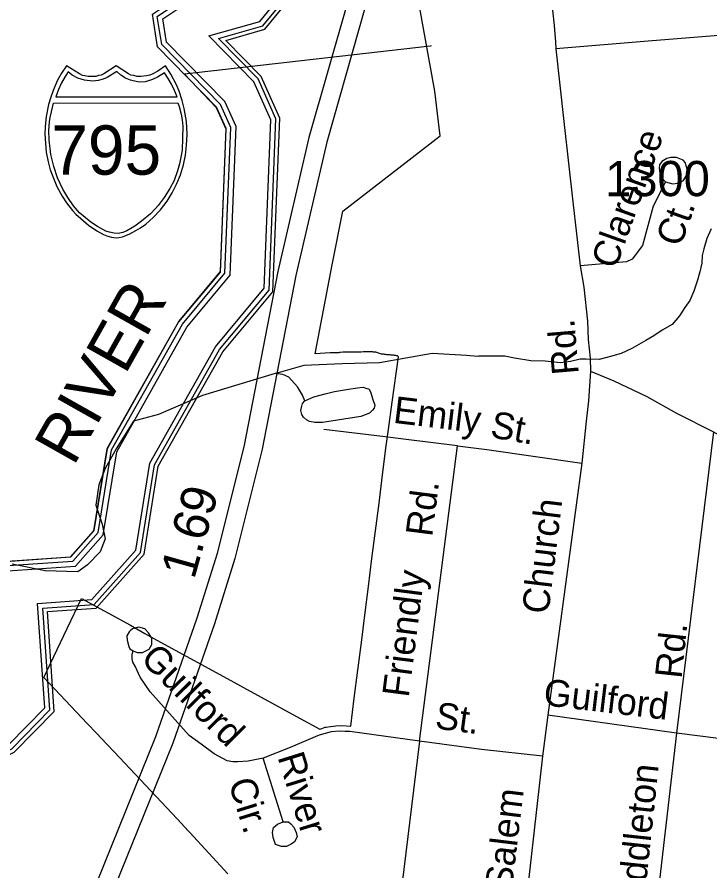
# Model space of a CAD drawing. Extents: x 2260773 to 2342389, y 552869 to 618546.
# Drawn here: x 2296402 to 2298862, y 604542 to 607573 of the extents above; entities that cross this region are included whole.
import ezdxf

# ---------------------------------------------------------------- set-up
doc = ezdxf.new("R2010")
doc.units = 0
for name, color, linetype in [('Exist Boundary Political City Limit New', 7, 'Continuous'), ('Exist Boundary Political Urban Extension UEB', 7, 'Continuous'), ('Exist Hydrographic Buffer Line', 7, 'Continuous'), ('Exist Hydrographic Misc Water Feature', 7, 'Continuous'), ('Exist Hydrographic River Shore', 7, 'Continuous'), ('Exist Hydrographic River Shore Label', 7, 'Continuous'), ('Exist Road Non-System Type 51', 7, 'Continuous'), ('Exist Road Non-System Type 51 Label', 7, 'Continuous'), ('Exist Road Primary Interstate Divided Center Attributed', 7, 'Continuous'), ('Exist Road Primary Interstate Service Mileage Tenths English Label', 7, 'Continuous'), ('Exist Road Primary Interstate Shield CELL', 7, 'Continuous'), ('Exist Road Primary Interstate Shield Number Label', 7, 'Continuous'), ('Exist Road Secondary Type 51 Attributed', 7, 'Continuous'), ('Exist Road Secondary Type 51 Label', 7, 'Continuous'), ('Exist Road Secondary Type 51 Number Label', 7, 'Continuous'), ('Map Preparation Boundary City Limit Buffer Line', 7, 'Continuous')]:
    doc.layers.add(name, color=color, linetype=linetype)

msp = doc.modelspace()

# ---------------------------------------------------------------- linework, layer by layer
at = {"layer": 'Exist Boundary Political City Limit New'}
for points in [[(2297696.2, 606376.5), (2297693.2, 606377.2), (2297689.5, 606378.7), (2297685.8, 606379.9), (2297683, 606380.9), (2297680, 606381.8), (2297676.2, 606382.8), (2297672.2, 606383.1), (2297668.2, 606383.4), (2297664.2, 606384.2), (2297660.5, 606384.6), (2297657.5, 606384.5), (2297654.5, 606384.4), (2297646.5, 606384.2), (2297642.5, 606384.3), (2297638.5, 606384.5), (2297635.5, 606384.4), (2297632.5, 606384.2), (2297624.5, 606383.8), (2297621.5, 606383.6), (2297618.5, 606383.5), (2297614.5, 606383.5), (2297610.5, 606383.6), (2297606.5, 606383.7), (2297602.5, 606383.8), (2297598.5, 606383.8), (2297595.5, 606383.8), (2297592.5, 606383.8), (2297588.5, 606383.6), (2297584.5, 606383.3), (2297580.5, 606383.1), (2297576.5, 606383.2), (2297572.5, 606383.5), (2297568.5, 606383.6), (2297564.5, 606383.7), (2297561.5, 606383.5), (2297558.5, 606383.2), (2297550.5, 606382.2), (2297547.5, 606381.8), (2297544.5, 606381.4), (2297540.5, 606381.2), (2297536.5, 606381.2), (2297532.5, 606381.3), (2297522.5, 606381.3), (2297514.5, 606381.1), (2297460.8, 606377.7), (2297521.5, 606693.6), (2297559.5, 606884.2), (2297904.8, 607151.4), (2297886.2, 607310.1), (2297774, 607926.1)], [(2297151, 604531.2), (2297015.2, 604677.7), (2297011, 604682.2), (2296970.5, 604725.9), (2296747.2, 604964.4), (2296719.8, 604993.1), (2296685.5, 605029.5), (2296651.5, 605065.4), (2296496.8, 605228.8), (2296580.2, 605402.7), (2296631.5, 605508.9), (2296805.2, 605413.8), (2296856.2, 605384.6), (2296899.2, 605360.9), (2297161.5, 605217.2), (2297206.2, 605192.8), (2297407.2, 605083.2), (2297477.2, 605044.9), (2297484.5, 605047.6), (2297496, 605051.9), (2297500, 605052.4), (2297515.2, 605054.7), (2297534, 605056.9), (2297555, 605057.8), (2297587.5, 605055.6), (2297599.8, 605154.9), (2297612.2, 605253.8), (2297624.8, 605352.5), (2297637.2, 605449.9), (2297650, 605550.9), (2297662.5, 605650.3), (2297675, 605749.3), (2297687.5, 605847.4), (2297700, 605948.2), (2297713, 606050.9), (2297721.5, 606109.2), (2297734.5, 606205.7), (2297756.2, 606366.8), (2297752.8, 606370.2), (2297750, 606370.9), (2297747, 606371.3), (2297743, 606371.9), (2297739, 606372.4), (2297735, 606372.8), (2297731, 606373.2), (2297727, 606373.4), (2297723, 606373.6), (2297719, 606373.8), (2297715, 606374.2), (2297711.2, 606374.8), (2297707.2, 606375.2), (2297703.2, 606375.8), (2297699.2, 606376.1), (2297696.2, 606376.5)]]:
    msp.add_lwpolyline(points, dxfattribs=at)
at = {"layer": 'Exist Boundary Political Urban Extension UEB'}
msp.add_line((2297872.5, 607470.4), (2297868.7, 607470), dxfattribs=at)
msp.add_lwpolyline([(2297868.7, 607470), (2296996.9, 607370.9), (2297109.4, 607251.9), (2297143.4, 607175.8), (2297123.3, 606667.8), (2296975.3, 606490.5), (2296721.4, 606039.8), (2296674.3, 605748.9), (2296591.4, 605655.4), (2296296, 605634.7)], dxfattribs=at)
at = {"layer": 'Exist Hydrographic Buffer Line'}
for points in [[(2296475, 605491.4), (2296668, 605505), (2296823.6, 605680.5), (2296873.6, 605988.8), (2297106.7, 606402.6), (2297279.8, 606610), (2297303.4, 607208.1), (2297242.9, 607343.6), (2297083.4, 607506.2), (2297264.1, 607557.4), (2297395.8, 607717.8), (2297494.3, 607907.7), (2297504.1, 608392.7)], [(2296494.4, 605474.7), (2296676.6, 605487.4), (2296840.6, 605672.5), (2296890.9, 605982.8), (2297121.6, 606392.3), (2297297.6, 606603.1), (2297321.7, 607211.6), (2297258, 607353.9), (2297117.7, 607497.1), (2297274.5, 607541.5), (2297411, 607707.8), (2297512.3, 607903.2), (2297522.4, 608402.3)], [(2296298.6, 605620.6), (2296600.6, 605641.8), (2296690.8, 605743.6), (2296738.2, 606036.2), (2296990, 606483.2), (2297140.5, 606663.6), (2297161, 607180.7), (2297124.3, 607262.8), (2296915.9, 607475.3), (2296900.2, 607575.4), (2296964.8, 607619.3), (2297183, 607681.2), (2297277.2, 607795.9), (2297353.7, 607943.5), (2297359.6, 608229.5)], [(2296299.9, 605601.9), (2296609.5, 605623.6), (2296708.4, 605735.2), (2296756.2, 606030), (2297005.5, 606472.5), (2297159, 606656.5), (2297179.9, 607184.3), (2297140, 607273.5), (2296933.5, 607484.2), (2296920.5, 607566.6), (2296972.8, 607602.1), (2297193.8, 607664.7), (2297293, 607785.5), (2297372.4, 607938.8), (2297378.3, 608229.1)], [(2294622.7, 604572.8), (2294697.8, 604716.4), (2294813.4, 604644.1), (2295136.8, 604692.7), (2295597, 604923.2), (2296195.9, 604904.5), (2296373.2, 604989.9), (2296500.5, 605120.2), (2296475, 605491.4)], [(2294638.6, 604563.9), (2294704.9, 604690.5), (2294809.4, 604625.1), (2295142.4, 604675.1), (2295601.1, 604904.8), (2296199.8, 604886.1), (2296384, 604974.9), (2296519.2, 605113.3), (2296494.4, 605474.7)]]:
    msp.add_lwpolyline(points, dxfattribs=at)
at = {"layer": 'Exist Hydrographic Misc Water Feature'}
for points in [[(2298866.4, 606821.2), (2298851, 606787), (2298841.2, 606750.8), (2298835.4, 606726.9), (2298833.8, 606698.8), (2298826.2, 606668.7), (2298818.6, 606638.6), (2298805.1, 606600.5), (2298791.3, 606566.5), (2298773.7, 606542.4), (2298754.2, 606512), (2298728.4, 606481.9), (2298692.7, 606461.3), (2298663, 606441), (2298634.7, 606425), (2298585.3, 606396.3), (2298547.5, 606378.1), (2298509.6, 606367.6), (2298469.6, 606357), (2298423.5, 606358.6), (2298401.7, 606358.3), (2298367.7, 606350), (2298332, 606345.7), (2298277.7, 606351), (2298226, 606352.3), (2298168.2, 606361.8), (2298133.7, 606369.5), (2298100.1, 606369.3), (2298074.1, 606368.7), (2298042.3, 606368.6), (2298038.4, 606368.4)], [(2298038.4, 606368.4), (2297998.2, 606372), (2297876, 606379), (2297689, 606345.2), (2297557.1, 606341.9), (2297421, 606336.4), (2297329.1, 606309.7), (2297319.3, 606307.6)], [(2297319.3, 606307.6), (2297189.5, 606268.3), (2297060.3, 606229.4), (2296904.9, 606161.9), (2296815.2, 606138.9)], [(2297424.3, 606210.6), (2297415.6, 606230.6), (2297397.8, 606260.5), (2297367.7, 606294.2), (2297345.5, 606304), (2297319.3, 606307.6)], [(2297424.3, 606210.6), (2297456, 606225), (2297496, 606235.6), (2297529.6, 606243.9), (2297579.5, 606252.2), (2297611.7, 606256.6), (2297631.6, 606258.5), (2297643.7, 606254.7), (2297651.4, 606252.7), (2297657.4, 606242.8), (2297666, 606215.2), (2297672.2, 606195.2), (2297669.9, 606185), (2297664.4, 606176.9), (2297654.3, 606167.1), (2297622.9, 606154.8), (2297540.7, 606142), (2297487.2, 606133.4), (2297459.1, 606133.2), (2297440.9, 606136.8), (2297430.4, 606142.8), (2297418.9, 606152.7), (2297413, 606162.5), (2297410.5, 606176.6), (2297412.2, 606186.5), (2297416.3, 606200.5), (2297424.3, 606210.6)], [(2296815.2, 606138.9), (2296754.3, 606040.7), (2296715, 605970.3), (2296693.2, 605911.9), (2296682.2, 605839.8), (2296704.9, 605772.3), (2296715.4, 605720.5), (2296698, 605674), (2296652.4, 605627.7), (2296618.6, 605603.6), (2296502.1, 605606.6), (2296384.4, 605631.2)]]:
    msp.add_lwpolyline(points, dxfattribs=at)
at = {"layer": 'Exist Hydrographic River Shore'}
for points in [[(2296509.9, 605462.2), (2296683.1, 605474.4), (2296853.3, 605666.4), (2296903.9, 605978.2), (2297132.8, 606384.6), (2297310.9, 606598), (2297335.3, 607214.3), (2297269.4, 607361.6), (2297143.2, 607490.3), (2297282.2, 607529.7), (2297422.3, 607700.3), (2297525.7, 607899.7), (2297536.1, 608412.7)], [(2296297.5, 605636.5), (2296593, 605657.2), (2296675.8, 605750.7), (2296723, 606041.6), (2296976.8, 606492.3), (2297124.9, 606669.6), (2297145, 607177.6), (2297110.9, 607253.7), (2296901, 607467.8), (2296882.9, 607582.9), (2296958, 607633.9), (2297173.9, 607695.1), (2297263.9, 607804.7), (2297337.9, 607947.5), (2297343.7, 608229.8)], [(2294651.5, 604557.2), (2294710.5, 604669.8), (2294806.3, 604609.9), (2295146.8, 604661.1), (2295604.3, 604890.1), (2296202.9, 604871.5), (2296392.6, 604962.9), (2296534.2, 605107.8), (2296509.9, 605462.2)]]:
    msp.add_lwpolyline(points, dxfattribs=at)
at = {"layer": 'Exist Road Non-System Type 51'}
for p, q in [((2297699.9, 606083.4), (2297491.4, 606108.8)), ((2298875.5, 606100.5), (2298744.2, 605031.1)), ((2297783.9, 606073.2), (2297699.9, 606083.4)), ((2297965.7, 606051.1), (2297783.9, 606073.2)), ((2297831.6, 605002.4), (2297965.7, 606051.1)), ((2298744.2, 605031.1), (2298286.5, 605094.4)), ((2297346.6, 604716), (2297276.6, 604941.3))]:
    msp.add_line(p, q, dxfattribs=at)
for points in [[(2298704.3, 606988.5), (2298730.4, 606980.8), (2298748.3, 606983.1), (2298768.3, 606993.3), (2298782, 607015.5), (2298781.7, 607033.5), (2298777.6, 607045.3), (2298775.6, 607055.2), (2298767.4, 607065.3), (2298743.4, 607074.9), (2298723.4, 607074.7), (2298709.4, 607070.6), (2298691.6, 607060.4), (2298683.7, 607048.3), (2298681.8, 607036.2), (2298684.1, 607018.3), (2298692.1, 607002.4), (2298704.3, 606988.5)], [(2298704.3, 606988.5), (2298661.2, 606902.2), (2298623.4, 606762), (2298586.4, 606714), (2298566.4, 606703.7), (2298402.1, 606689.7)], [(2297965.7, 606051.1), (2298070.3, 606037.9), (2298407.2, 605989.2)], [(2299263.3, 605872.5), (2299145.6, 604980.3), (2298744.2, 605031.1)], [(2296804, 605393.6), (2296800.5, 605390.6), (2296792.6, 605376.6), (2296792.9, 605360.6), (2296799.1, 605338.7), (2296803.1, 605330.6), (2296815.1, 605322.8)], [(2296881, 605348.3), (2296880.8, 605367.4), (2296868.6, 605387.3), (2296856.5, 605401.1), (2296834.4, 605406.9), (2296812.5, 605400.8), (2296804, 605393.6)], [(2296833.7, 605316.9), (2296847.2, 605317.1), (2296871, 605329.2), (2296881, 605345.4), (2296881, 605348.3)], [(2297276.6, 604941.3), (2297222.6, 604930.8), (2297186.8, 604928.6), (2297168.8, 604928.3), (2297148.7, 604932.1), (2297102.4, 604957.7), (2297056.1, 604991.2), (2297014, 605022.8), (2296874.5, 605177.4), (2296840, 605229.1), (2296821.6, 605268.9), (2296813.5, 605282.8), (2296811.6, 605294.7), (2296811.3, 605310.7), (2296815.1, 605322.8)], [(2296815.1, 605322.8), (2296829.2, 605316.9), (2296833.7, 605316.9)], [(2297566.3, 605036.9), (2297547.5, 605037.8), (2297517.4, 605035.6), (2297475.6, 605023.1), (2297469.6, 605020.6)], [(2297831.6, 605002.4), (2297583.4, 605036.1), (2297566.3, 605036.9)], [(2298744.2, 605031.1), (2298663.6, 604335), (2298650.9, 604270), (2298635.4, 604229), (2298595.8, 604175.3), (2298512.5, 604069.3), (2298433.4, 603983), (2298395.9, 603952.3), (2298343, 603932.1), (2298273.7, 603926.5), (2298150.1, 603935.3)], [(2297469.6, 605020.6), (2297372.2, 604980.2), (2297276.6, 604941.3)], [(2297831.6, 605002.4), (2297761.1, 604432.1), (2297763.3, 604412.2), (2297767.4, 604400.2), (2297777.5, 604384.4), (2297789.5, 604374.5), (2297823.7, 604366.8), (2298053.4, 604323.7), (2298196.1, 604308.1)], [(2298268.5, 604949), (2298051.7, 604972.6), (2297831.6, 605002.4)], [(2297346.6, 604716), (2297366.6, 604716.2), (2297374.6, 604708.4), (2297384.8, 604696.4), (2297393, 604678.5), (2297397.1, 604662.6), (2297387.3, 604644.6), (2297375.4, 604636.4), (2297359.4, 604628.2), (2297341.4, 604628.1), (2297319.4, 604635.8), (2297311.1, 604659.7), (2297309, 604677.8), (2297312.8, 604695.7), (2297326.6, 604707.8), (2297346.6, 604716)]]:
    msp.add_lwpolyline(points, dxfattribs=at)
at = {"layer": 'Exist Road Primary Interstate Divided Center Attributed'}
for points in [[(2298844.5, 609852.1), (2298779.6, 609757.5), (2298564.9, 609447.7), (2298280.6, 609029.8), (2298078.5, 608714.6), (2297910.7, 608420), (2297811.4, 608214.4), (2297736.1, 608043.2), (2297575.1, 607625.2), (2297438.1, 607145.6), (2297328.5, 606669.4), (2297208.7, 606052.8), (2297112.8, 605669.1), (2297040.9, 605439.5), (2296893.6, 605018.2), (2296605.9, 604305.6), (2296386.7, 603730), (2296248.2, 603378.4), (2296202.7, 603264.5), (2296044.3, 602853), (2295787.4, 602202.1), (2295553.8, 601595.1)], [(2298862.1, 609753.4), (2298618.9, 609410.6), (2298335.4, 608993.6), (2298134.7, 608680.6), (2297968.8, 608389.4), (2297871, 608186.9), (2297796.7, 608018.1), (2297637.4, 607604.4), (2297501.7, 607129.2), (2297392.7, 606655.8), (2297272.7, 606038.5), (2297176, 605651.3), (2297103.1, 605418.9), (2296955, 604995), (2296667, 604281.6), (2296448.1, 603706.8), (2296328.1, 603387.7), (2296105.3, 602828.8), (2295848.5, 602178.3), (2295615.8, 601573.6)]]:
    msp.add_lwpolyline(points, dxfattribs=at)
at = {"layer": 'Exist Road Primary Interstate Shield CELL'}
for points in [[(2296754.2, 606789.7), (2296763.7, 606790.6), (2296776.5, 606793.1), (2296788.8, 606797.1), (2296802.9, 606803.4), (2296823.8, 606814.9), (2296840.5, 606824.7), (2296859.9, 606837.7), (2296886, 606861.4), (2296912, 606888.9), (2296935, 606919.9), (2296953.3, 606948.9), (2296969.4, 606982.1), (2296982.8, 607013), (2296993.5, 607048.3), (2297000.5, 607082.5), (2297004.1, 607118.2), (2297006.5, 607157.8), (2297003.8, 607202.4), (2296996, 607247.9), (2296988.8, 607276.3), (2296977.7, 607310.2), (2296968.7, 607331.9), (2296947.9, 607370.3), (2296929.2, 607399.9), (2296901.9, 607380.7), (2296884.2, 607371.3), (2296873.3, 607366.4), (2296862.2, 607364.3), (2296841.7, 607361.8), (2296828.8, 607362.3), (2296816.8, 607365.1), (2296806.7, 607367.3), (2296798.5, 607371.3), (2296754.2, 607399.9), (2296710, 607371.3), (2296700.7, 607367), (2296691.2, 607365.1), (2296682, 607362.5), (2296666.9, 607361.8), (2296655.3, 607362.1), (2296643.5, 607364.3), (2296634.1, 607366.2), (2296623.6, 607371.3), (2296578.4, 607399.9), (2296560.7, 607374.2), (2296546.2, 607348.8), (2296530.9, 607312.9), (2296521.3, 607285), (2296514.5, 607262.2), (2296506.2, 607220.2), (2296501.9, 607183.7), (2296501.1, 607157.8), (2296505.9, 607093.3), (2296512.9, 607058.9), (2296520.1, 607031.2), (2296544, 606971.1), (2296561.9, 606937.5), (2296577.3, 606913.3), (2296598.9, 606886.2), (2296610.6, 606873.2), (2296655.4, 606834), (2296685.4, 606813.6), (2296709.3, 606800.7), (2296720.5, 606796.4), (2296738.1, 606791.5)], [(2296583.8, 607379.2), (2296572.8, 607362.3), (2296560.1, 607339.4), (2296550, 607315.7), (2296539.6, 607289.6), (2296971.2, 607289.4), (2296961.2, 607311.9), (2296950.4, 607334.4), (2296939.1, 607354.9), (2296925.4, 607374.8), (2296901.2, 607359.6), (2296883.6, 607351.3), (2296869.4, 607346.4), (2296857.4, 607343.7), (2296838.8, 607342.2), (2296830.5, 607342.7), (2296804.6, 607348.6), (2296787, 607355.7), (2296770.3, 607366.9), (2296756.8, 607379.6), (2296722.6, 607358.9), (2296707.5, 607352.2), (2296690, 607347.8), (2296670.9, 607345.4), (2296641.5, 607348.6), (2296618.4, 607356.5), (2296598.5, 607366.9)], [(2296973.7, 607268.1), (2296978.4, 607255.9), (2296984.7, 607228.9), (2296988.1, 607208.1), (2296991.5, 607184.1), (2296990.3, 607142.9), (2296988.3, 607100.4), (2296984.4, 607075.1), (2296979.2, 607052.2), (2296972, 607026.7), (2296960.5, 606992.9), (2296944.6, 606964.3), (2296924.7, 606932.4), (2296903.2, 606904.6), (2296893.9, 606893), (2296876.2, 606874.3), (2296844, 606848.5), (2296820.4, 606830.9), (2296792.3, 606814.2), (2296777.9, 606807.9), (2296761.3, 606804.4), (2296747.6, 606805.4), (2296731, 606809.8), (2296717.5, 606813.4), (2296688.1, 606829.4), (2296664.2, 606845.3), (2296624.4, 606877.9), (2296603, 606903), (2296582.9, 606932.4), (2296565.1, 606962.5), (2296546, 607002.2), (2296532.5, 607042.1), (2296522.8, 607085.2), (2296516.2, 607137.8), (2296515.4, 607169.9), (2296517.4, 607200.7), (2296520.3, 607216.9), (2296524.2, 607236.9), (2296532.1, 607267.9)]]:
    msp.add_lwpolyline(points, close=True, dxfattribs=at)
at = {"layer": 'Exist Road Secondary Type 51 Attributed'}
for points in [[(2298326.3, 607902.4), (2298320.6, 607880.8), (2298315.2, 607857.3), (2298309.1, 607821.1), (2298305.7, 607792.5), (2298302.5, 607756.6), (2298300.3, 607714.1), (2298299.3, 607663.6), (2298304.1, 607597.5), (2298309.5, 607543.5), (2298314.2, 607485.4), (2298315.5, 607460.1)], [(2302573.1, 607056.5), (2302555.7, 607059.5), (2302514.8, 607063.8), (2302204.4, 607120.2), (2301760.8, 607205.2), (2301372.1, 607283.2), (2300991.4, 607343.2), (2300723.5, 607379.8), (2300350.2, 607435.5), (2300073.5, 607473.6), (2299877.3, 607500), (2299662.1, 607516.6), (2299504.7, 607526.3), (2299403.7, 607530.7), (2299340.7, 607530.7), (2299273.4, 607532.2), (2299137.4, 607527.2), (2299130.2, 607526.9), (2298642.9, 607487.6), (2298315.5, 607460.1)], [(2298315.5, 607460.1), (2298344.1, 607202.6), (2298375.3, 606917), (2298402.1, 606689.7), (2298414.6, 606613.7), (2298427.8, 606493.8), (2298430.5, 606427.9), (2298436.9, 606362.3), (2298439, 606315.7)], [(2298439, 606315.7), (2298430.9, 606210.1), (2298423.6, 606138), (2298407.2, 605989.2), (2298286.5, 605094.4), (2298268.5, 604949), (2298196.1, 604308.1), (2298150.1, 603935.3), (2298124.7, 603738.1), (2298109.9, 603570.6), (2298110.1, 603317.9), (2298127.6, 603170.2), (2298167.9, 602956.8), (2298250.4, 602544), (2298308.7, 602254.2), (2298357.8, 602203.1), (2298421.4, 602171.3), (2298523.1, 602133.1)], [(2298439, 606315.7), (2298521.7, 606281.8), (2298638.2, 606225.6), (2298744.2, 606166.2), (2298875.5, 606100.5), (2299197.6, 605916), (2299263.3, 605872.5), (2299460.4, 605743.2), (2299617.2, 605643.6), (2299786.7, 605531.2), (2299909.6, 605444.2)]]:
    msp.add_lwpolyline(points, dxfattribs=at)
at = {"layer": 'Map Preparation Boundary City Limit Buffer Line'}
for points in [[(2297696.2, 606376.5), (2297693.2, 606377.2), (2297689.5, 606378.7), (2297685.8, 606379.9), (2297683, 606380.9), (2297680, 606381.8), (2297676.2, 606382.8), (2297672.2, 606383.1), (2297668.2, 606383.4), (2297664.2, 606384.2), (2297660.5, 606384.6), (2297657.5, 606384.5), (2297654.5, 606384.4), (2297646.5, 606384.2), (2297642.5, 606384.3), (2297638.5, 606384.5), (2297635.5, 606384.4), (2297632.5, 606384.2), (2297624.5, 606383.8), (2297621.5, 606383.6), (2297618.5, 606383.5), (2297614.5, 606383.5), (2297610.5, 606383.6), (2297606.5, 606383.7), (2297602.5, 606383.8), (2297598.5, 606383.8), (2297595.5, 606383.8), (2297592.5, 606383.8), (2297588.5, 606383.6), (2297584.5, 606383.3), (2297580.5, 606383.1), (2297576.5, 606383.2), (2297572.5, 606383.5), (2297568.5, 606383.6), (2297564.5, 606383.7), (2297561.5, 606383.5), (2297558.5, 606383.2), (2297550.5, 606382.2), (2297547.5, 606381.8), (2297544.5, 606381.4), (2297540.5, 606381.2), (2297536.5, 606381.2), (2297532.5, 606381.3), (2297522.5, 606381.3), (2297514.5, 606381.1), (2297460.8, 606377.7), (2297521.5, 606693.6), (2297559.5, 606884.2), (2297904.8, 607151.4), (2297886.2, 607310.1), (2297774, 607926.1)], [(2297151, 604531.2), (2297015.2, 604677.7), (2297011, 604682.2), (2296970.5, 604725.9), (2296747.2, 604964.4), (2296719.8, 604993.1), (2296685.5, 605029.5), (2296651.5, 605065.4), (2296496.8, 605228.8), (2296580.2, 605402.7), (2296631.5, 605508.9), (2296805.2, 605413.8), (2296856.2, 605384.6), (2296899.2, 605360.9), (2297161.5, 605217.2), (2297206.2, 605192.8), (2297407.2, 605083.2), (2297477.2, 605044.9), (2297484.5, 605047.6), (2297496, 605051.9), (2297500, 605052.4), (2297515.2, 605054.7), (2297534, 605056.9), (2297555, 605057.8), (2297587.5, 605055.6), (2297599.8, 605154.9), (2297612.2, 605253.8), (2297624.8, 605352.5), (2297637.2, 605449.9), (2297650, 605550.9), (2297662.5, 605650.3), (2297675, 605749.3), (2297687.5, 605847.4), (2297700, 605948.2), (2297713, 606050.9), (2297721.5, 606109.2), (2297734.5, 606205.7), (2297756.2, 606366.8), (2297752.8, 606370.2), (2297750, 606370.9), (2297747, 606371.3), (2297743, 606371.9), (2297739, 606372.4), (2297735, 606372.8), (2297731, 606373.2), (2297727, 606373.4), (2297723, 606373.6), (2297719, 606373.8), (2297715, 606374.2), (2297711.2, 606374.8), (2297707.2, 606375.2), (2297703.2, 606375.8), (2297699.2, 606376.1), (2297696.2, 606376.5)]]:
    msp.add_lwpolyline(points, dxfattribs=at)

# ---------------------------------------------------------------- texts
at = {"layer": 'Exist Hydrographic River Shore Label'}
msp.add_text('RIVER', height=167.32, rotation=60.6101, dxfattribs=at).set_placement((2296602.9, 605975.5))
at = {"layer": 'Exist Road Non-System Type 51 Label'}
for s, rotation, p in [('Clarence', 70.336, (2298527.8, 606674.3)), ('Ct.', 70.336, (2298757.5, 606753.2)), ('Emily', 353.0638, (2297735.3, 606132.9)), ('St.', 349.9481, (2298079.1, 606081.9)), ('Rd.', 82.7131, (2297876, 605725.5)), ('Friendly', 82.7131, (2297792.7, 605155)), ('Rd.', 83.9477, (2298761.6, 605222.1)), ('Guilford', 314.9215, (2296836.6, 605290.6)), ('Guilford', 353.1877, (2298268.3, 605130.5)), ('St.', 352.2894, (2297883.5, 605047.8)), ('River', 287.26, (2297326.6, 604946.2)), ('Middleton', 83.9477, (2298622.8, 604368.9)), ('Cir.', 287.26, (2297152, 604856.2))]:
    msp.add_text(s, height=95, rotation=rotation, dxfattribs=at).set_placement(p)
at = {"layer": 'Exist Road Primary Interstate Service Mileage Tenths English Label'}
msp.add_text('1.69', height=125, rotation=74.3186, dxfattribs=at).set_placement((2297031, 605573.6))
at = {"layer": 'Exist Road Primary Interstate Shield Number Label'}
msp.add_text('795', height=175, dxfattribs=at).set_placement((2296523.6, 607013.5))
at = {"layer": 'Exist Road Secondary Type 51 Label'}
for s, rotation, p in [('Rd.', 94.8685, (2298397.2, 606306.8)), ('Church', 83.0326, (2298288.9, 605450.9)), ('Salem', 83.1271, (2298158.6, 604471))]:
    msp.add_text(s, height=95, rotation=rotation, dxfattribs=at).set_placement(p)
at = {"layer": 'Exist Road Secondary Type 51 Number Label'}
msp.add_text('1300', height=125, dxfattribs=at).set_placement((2298490.3, 606937.2))

doc.saveas('drawing.dxf')
